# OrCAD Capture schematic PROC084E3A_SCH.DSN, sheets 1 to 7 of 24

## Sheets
1 17.LIN INTERFACE -03: size C; title: LIN INTERFACE-03; rev: E3A; note: PROC084_SCH
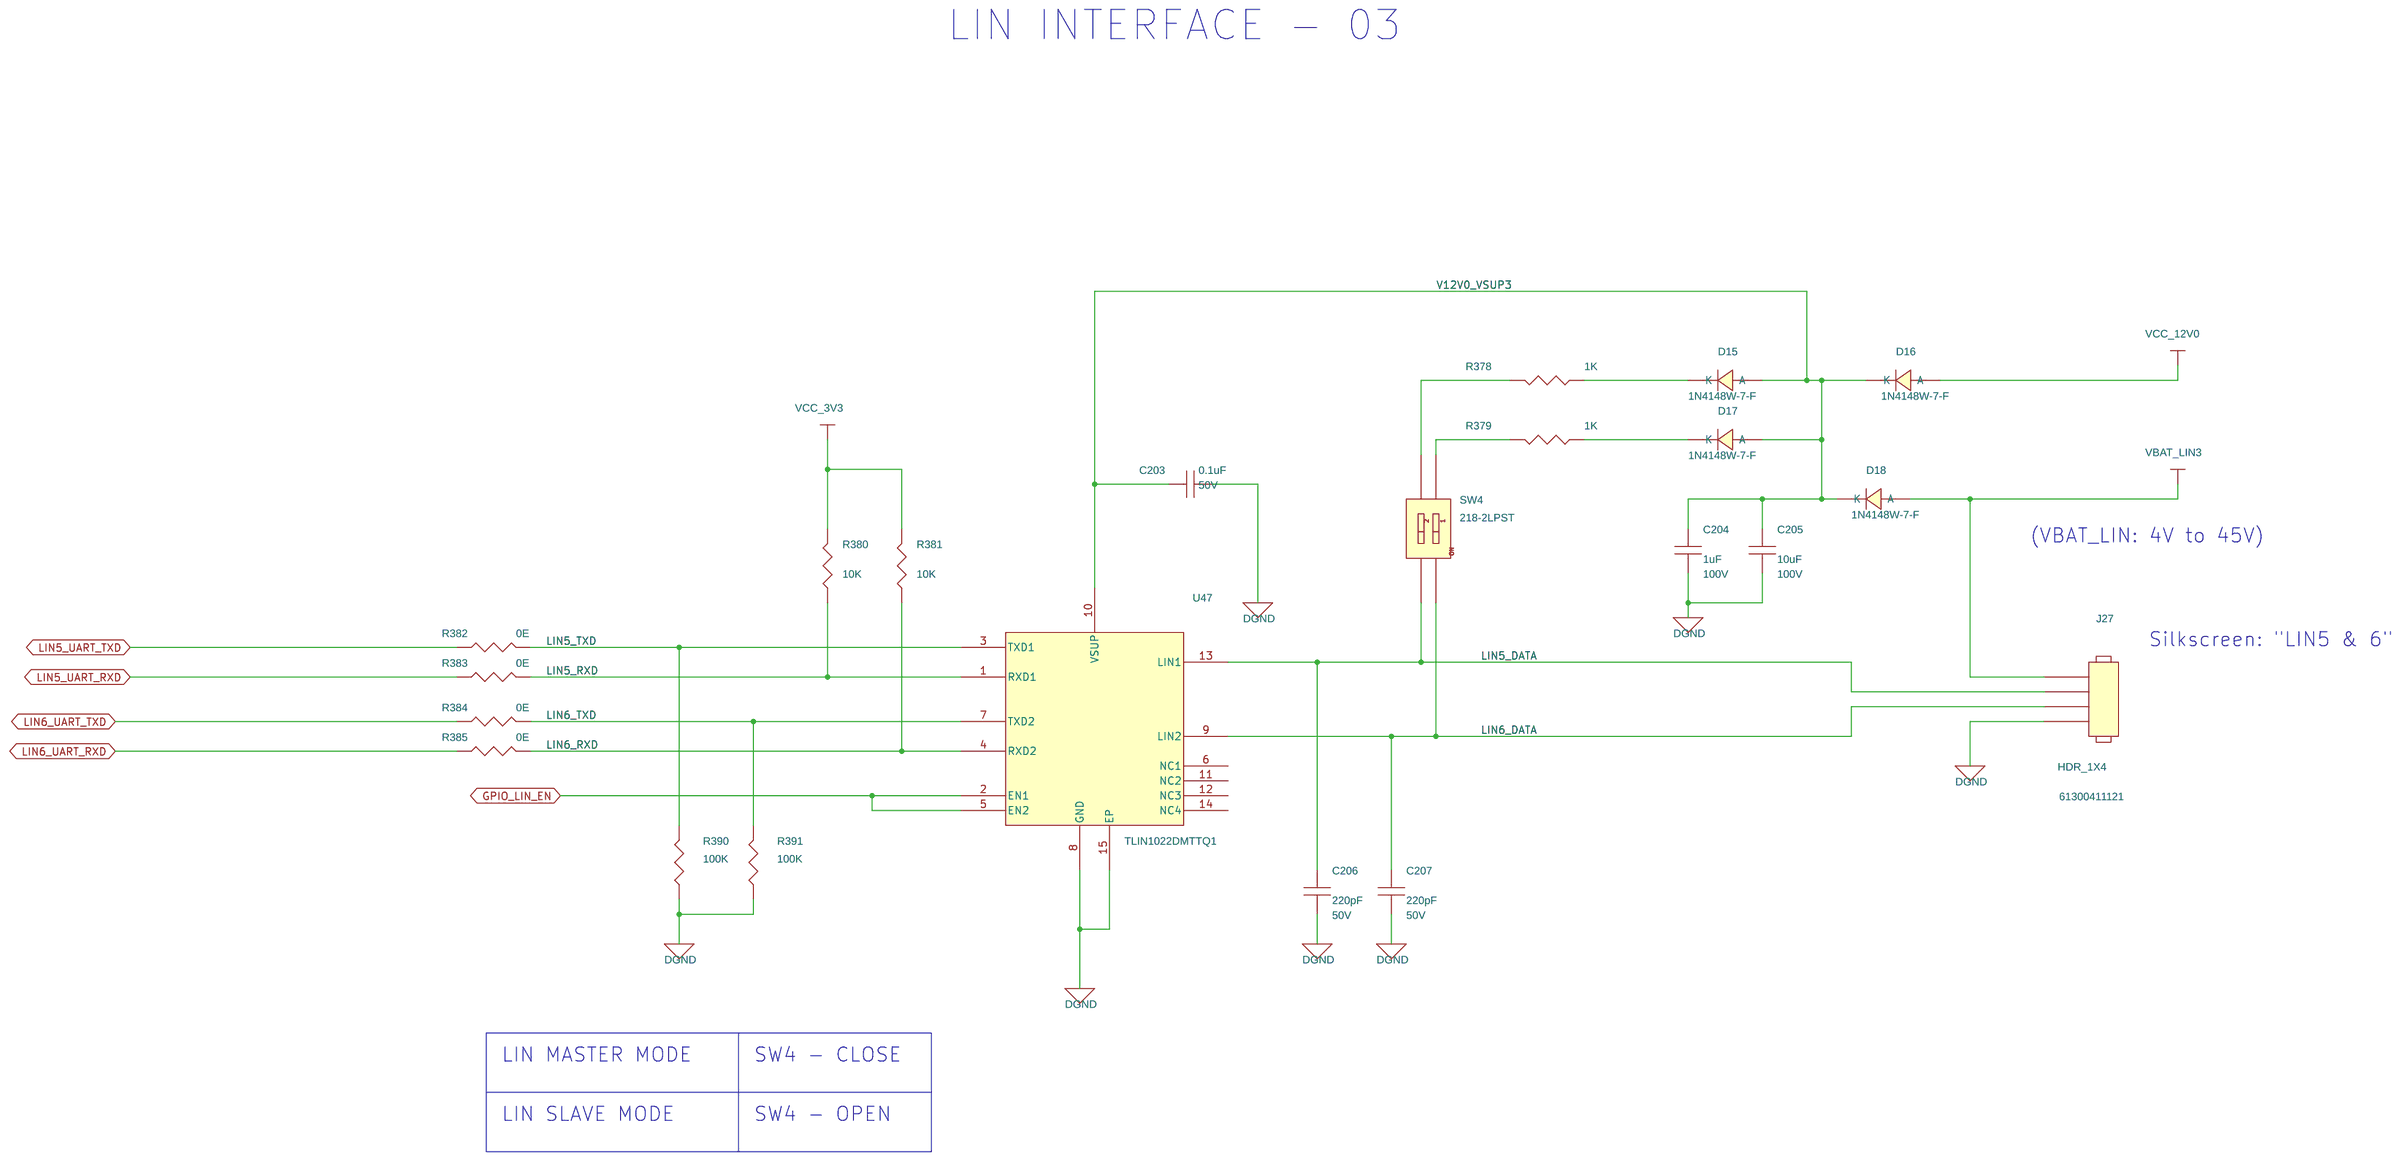
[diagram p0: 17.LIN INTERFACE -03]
2 16.LIN INTERFACE -02: size C; title: LIN INTERFACE-02
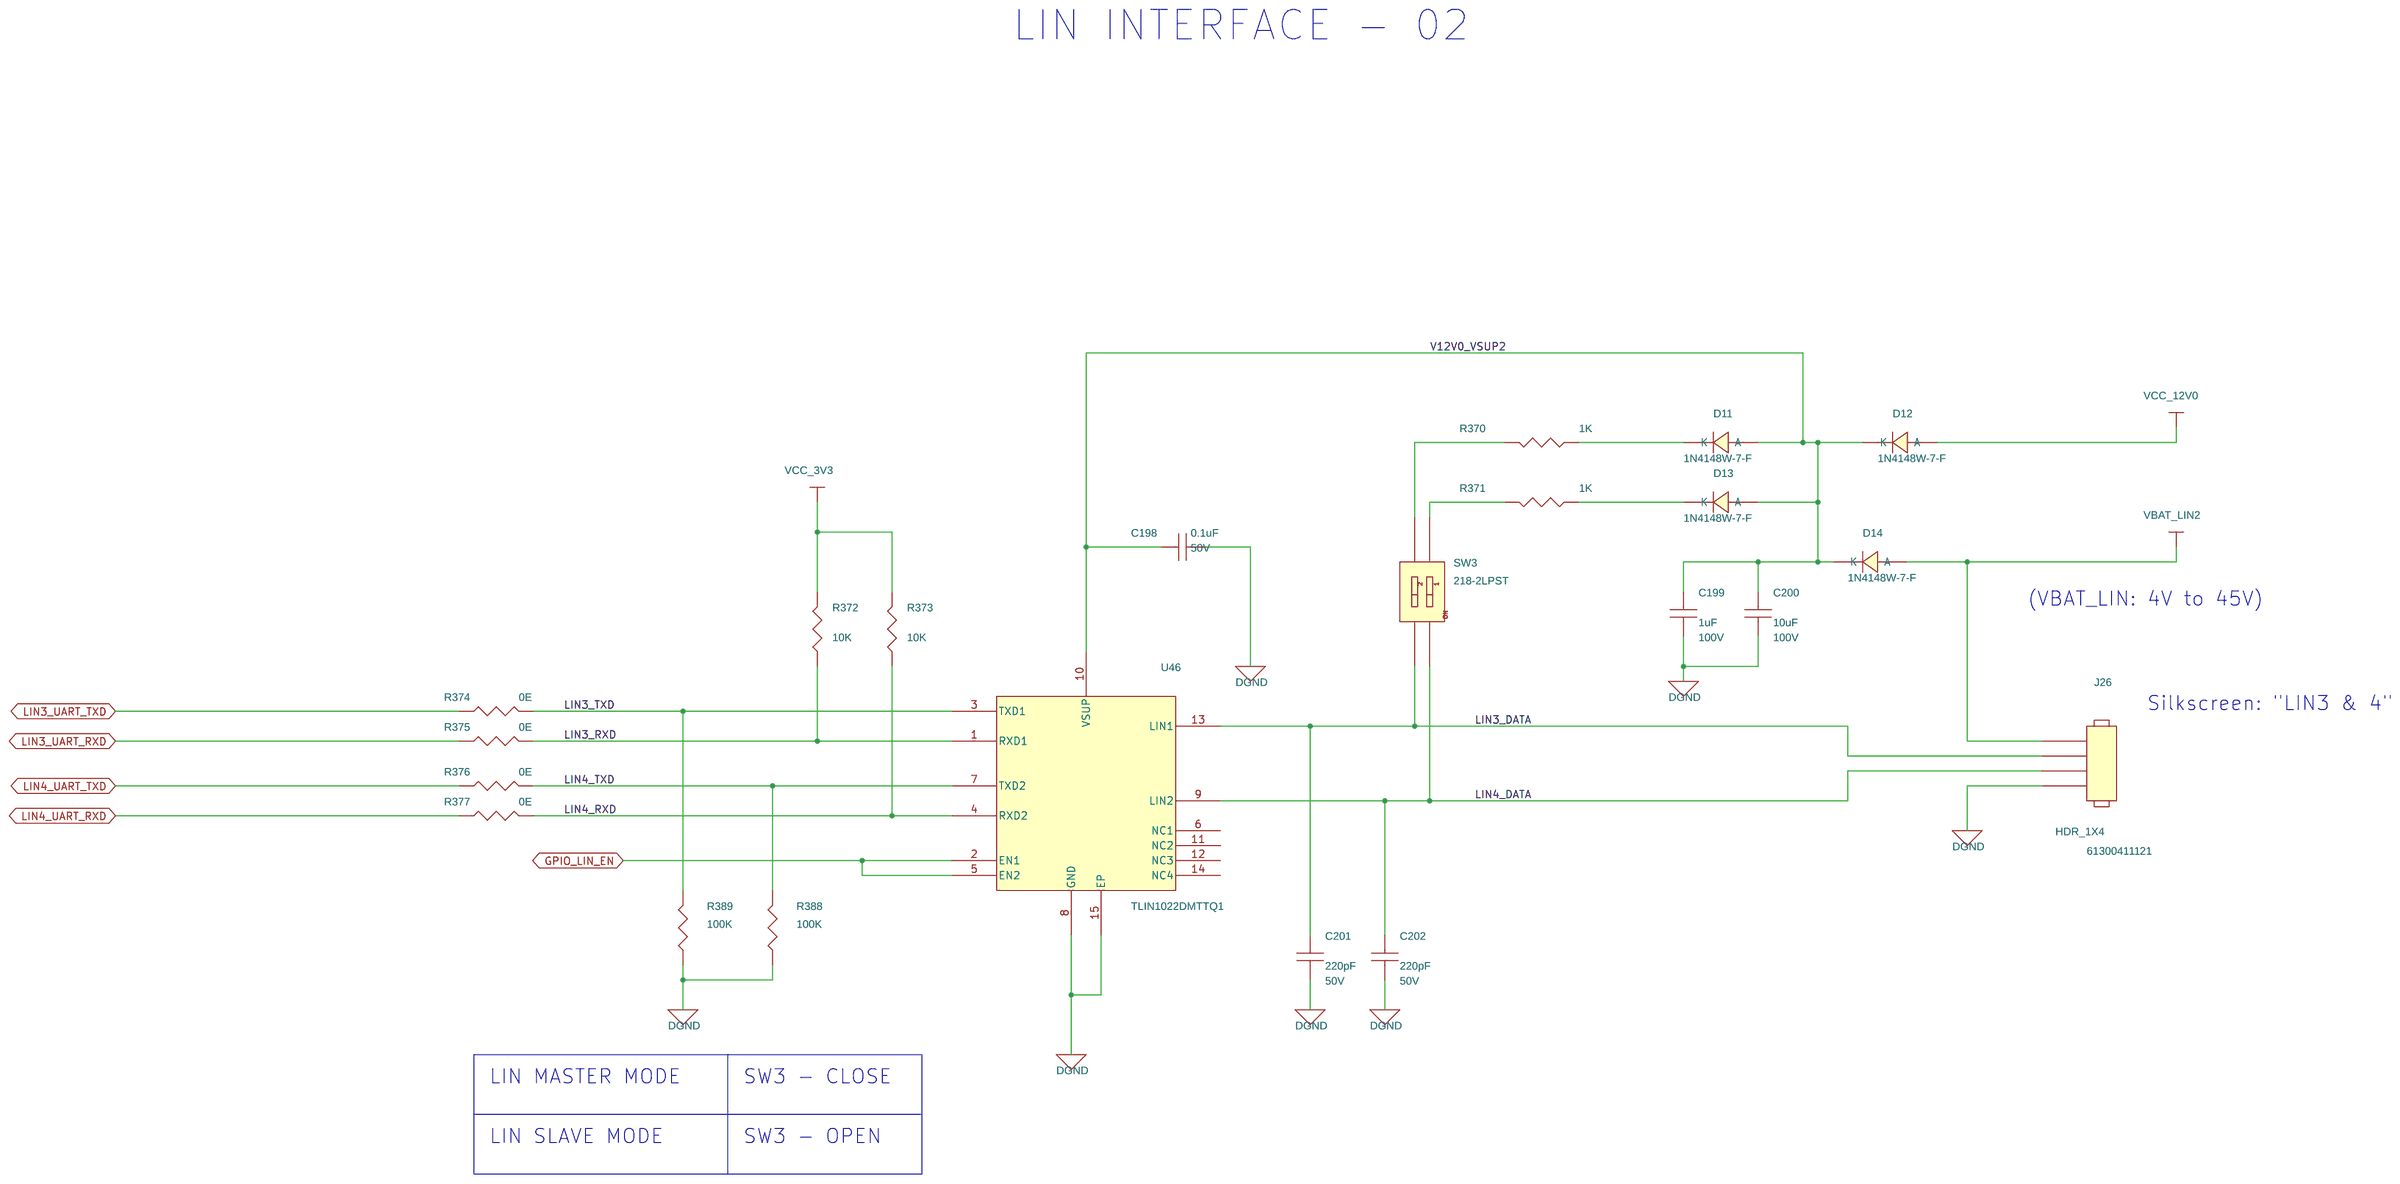
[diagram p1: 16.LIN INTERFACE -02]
3 15.LIN INTERFACE -01: size C; title: LIN INTERFACE-01
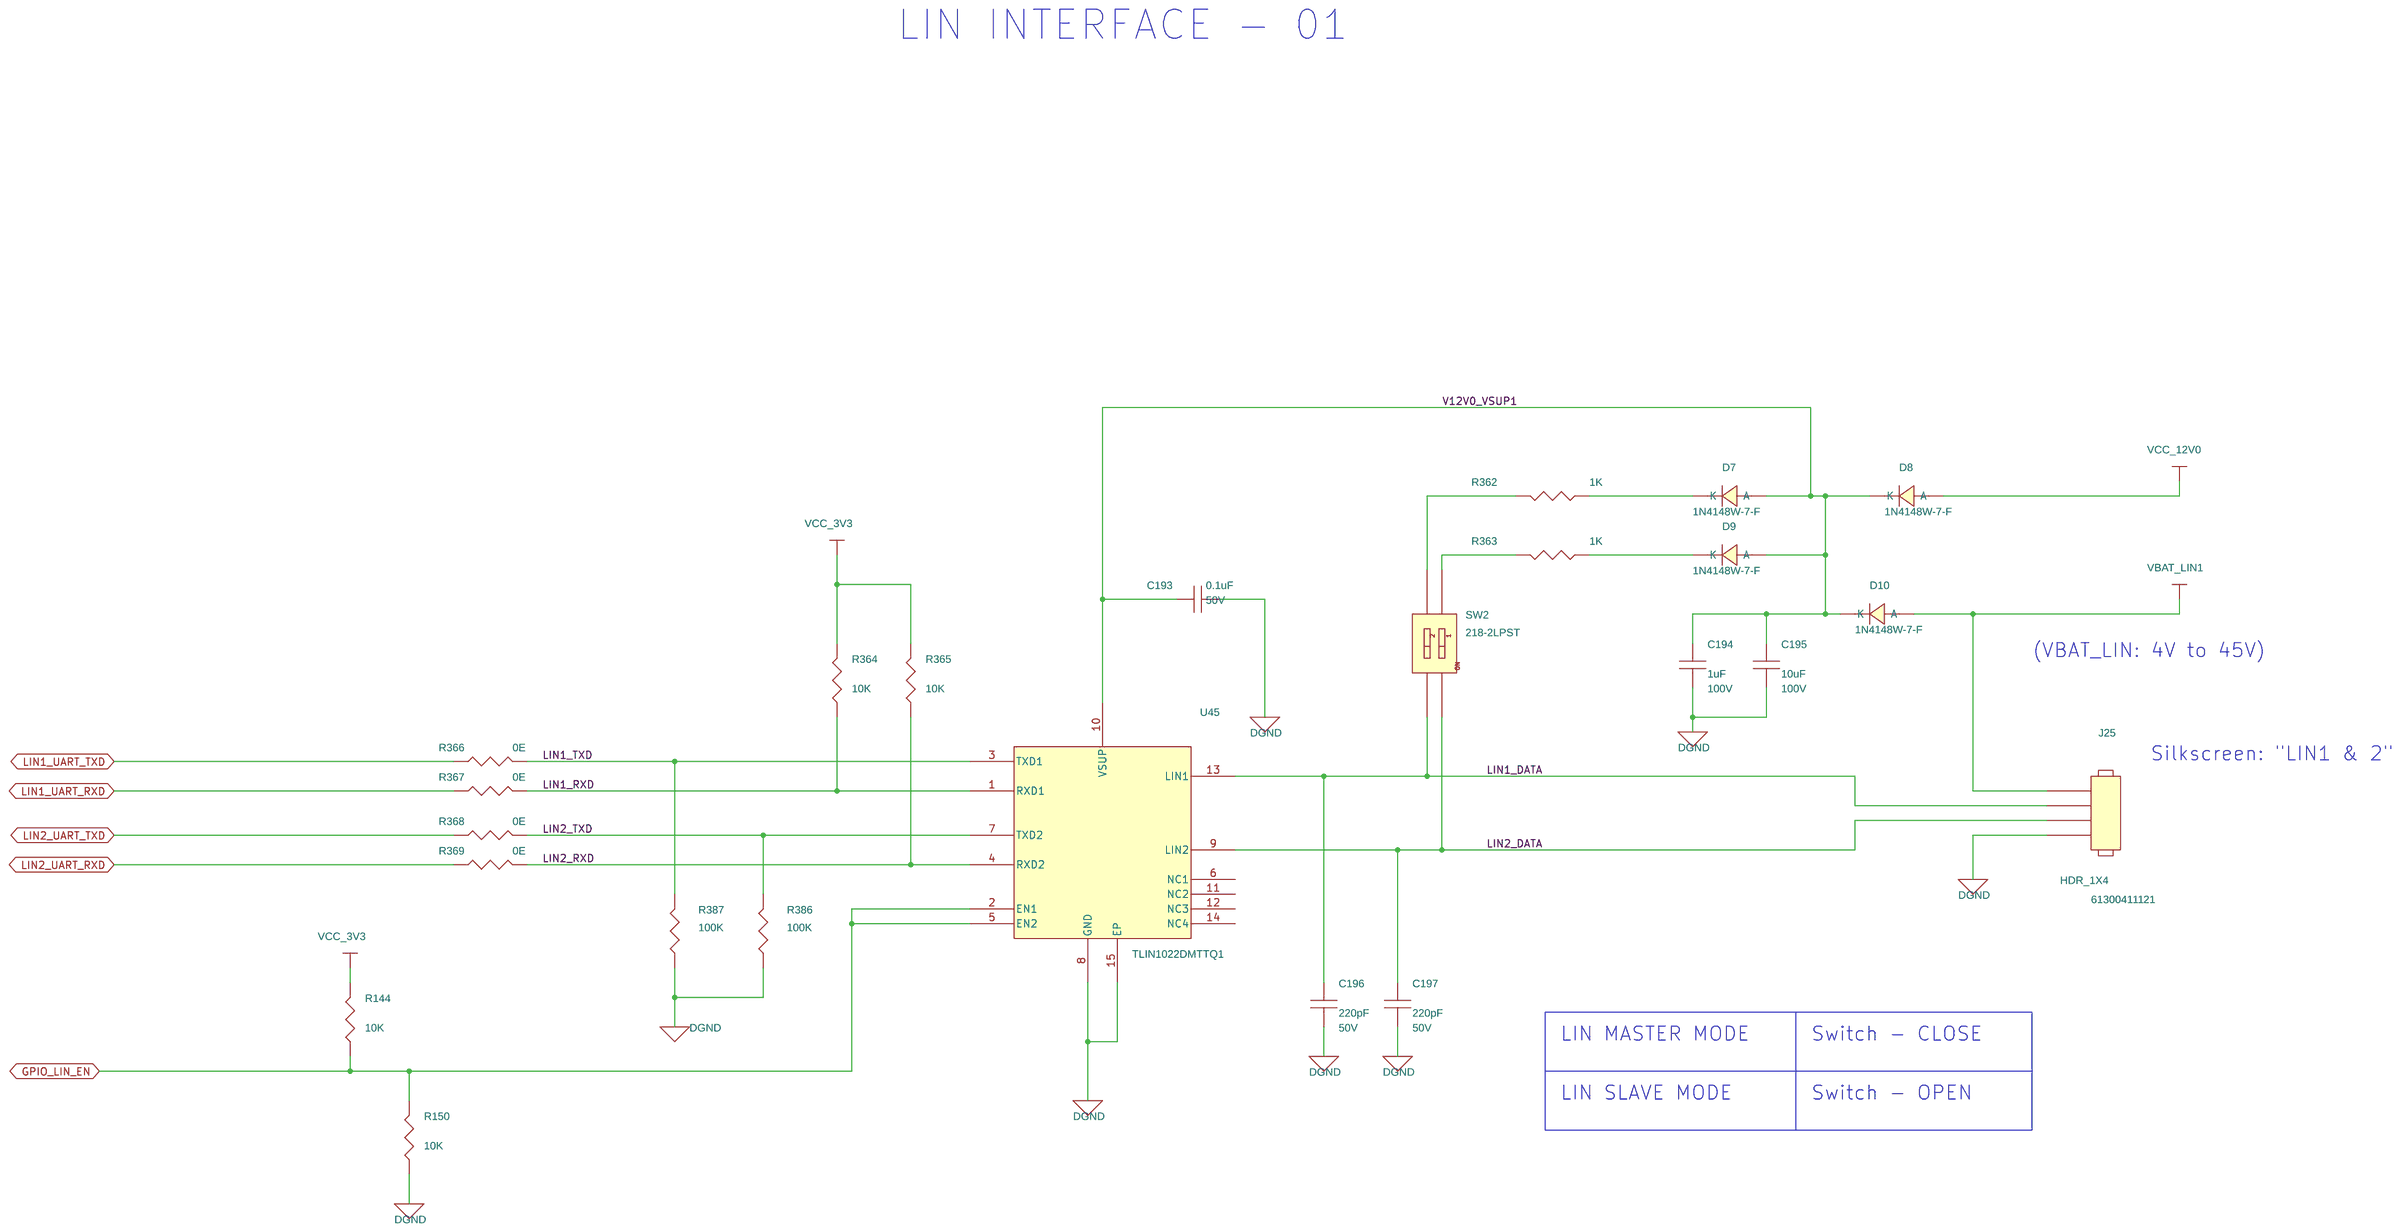
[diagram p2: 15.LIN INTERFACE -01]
4 24. HARDWARE SCHEMATICS: title: HARDWARE SCHEMATICS
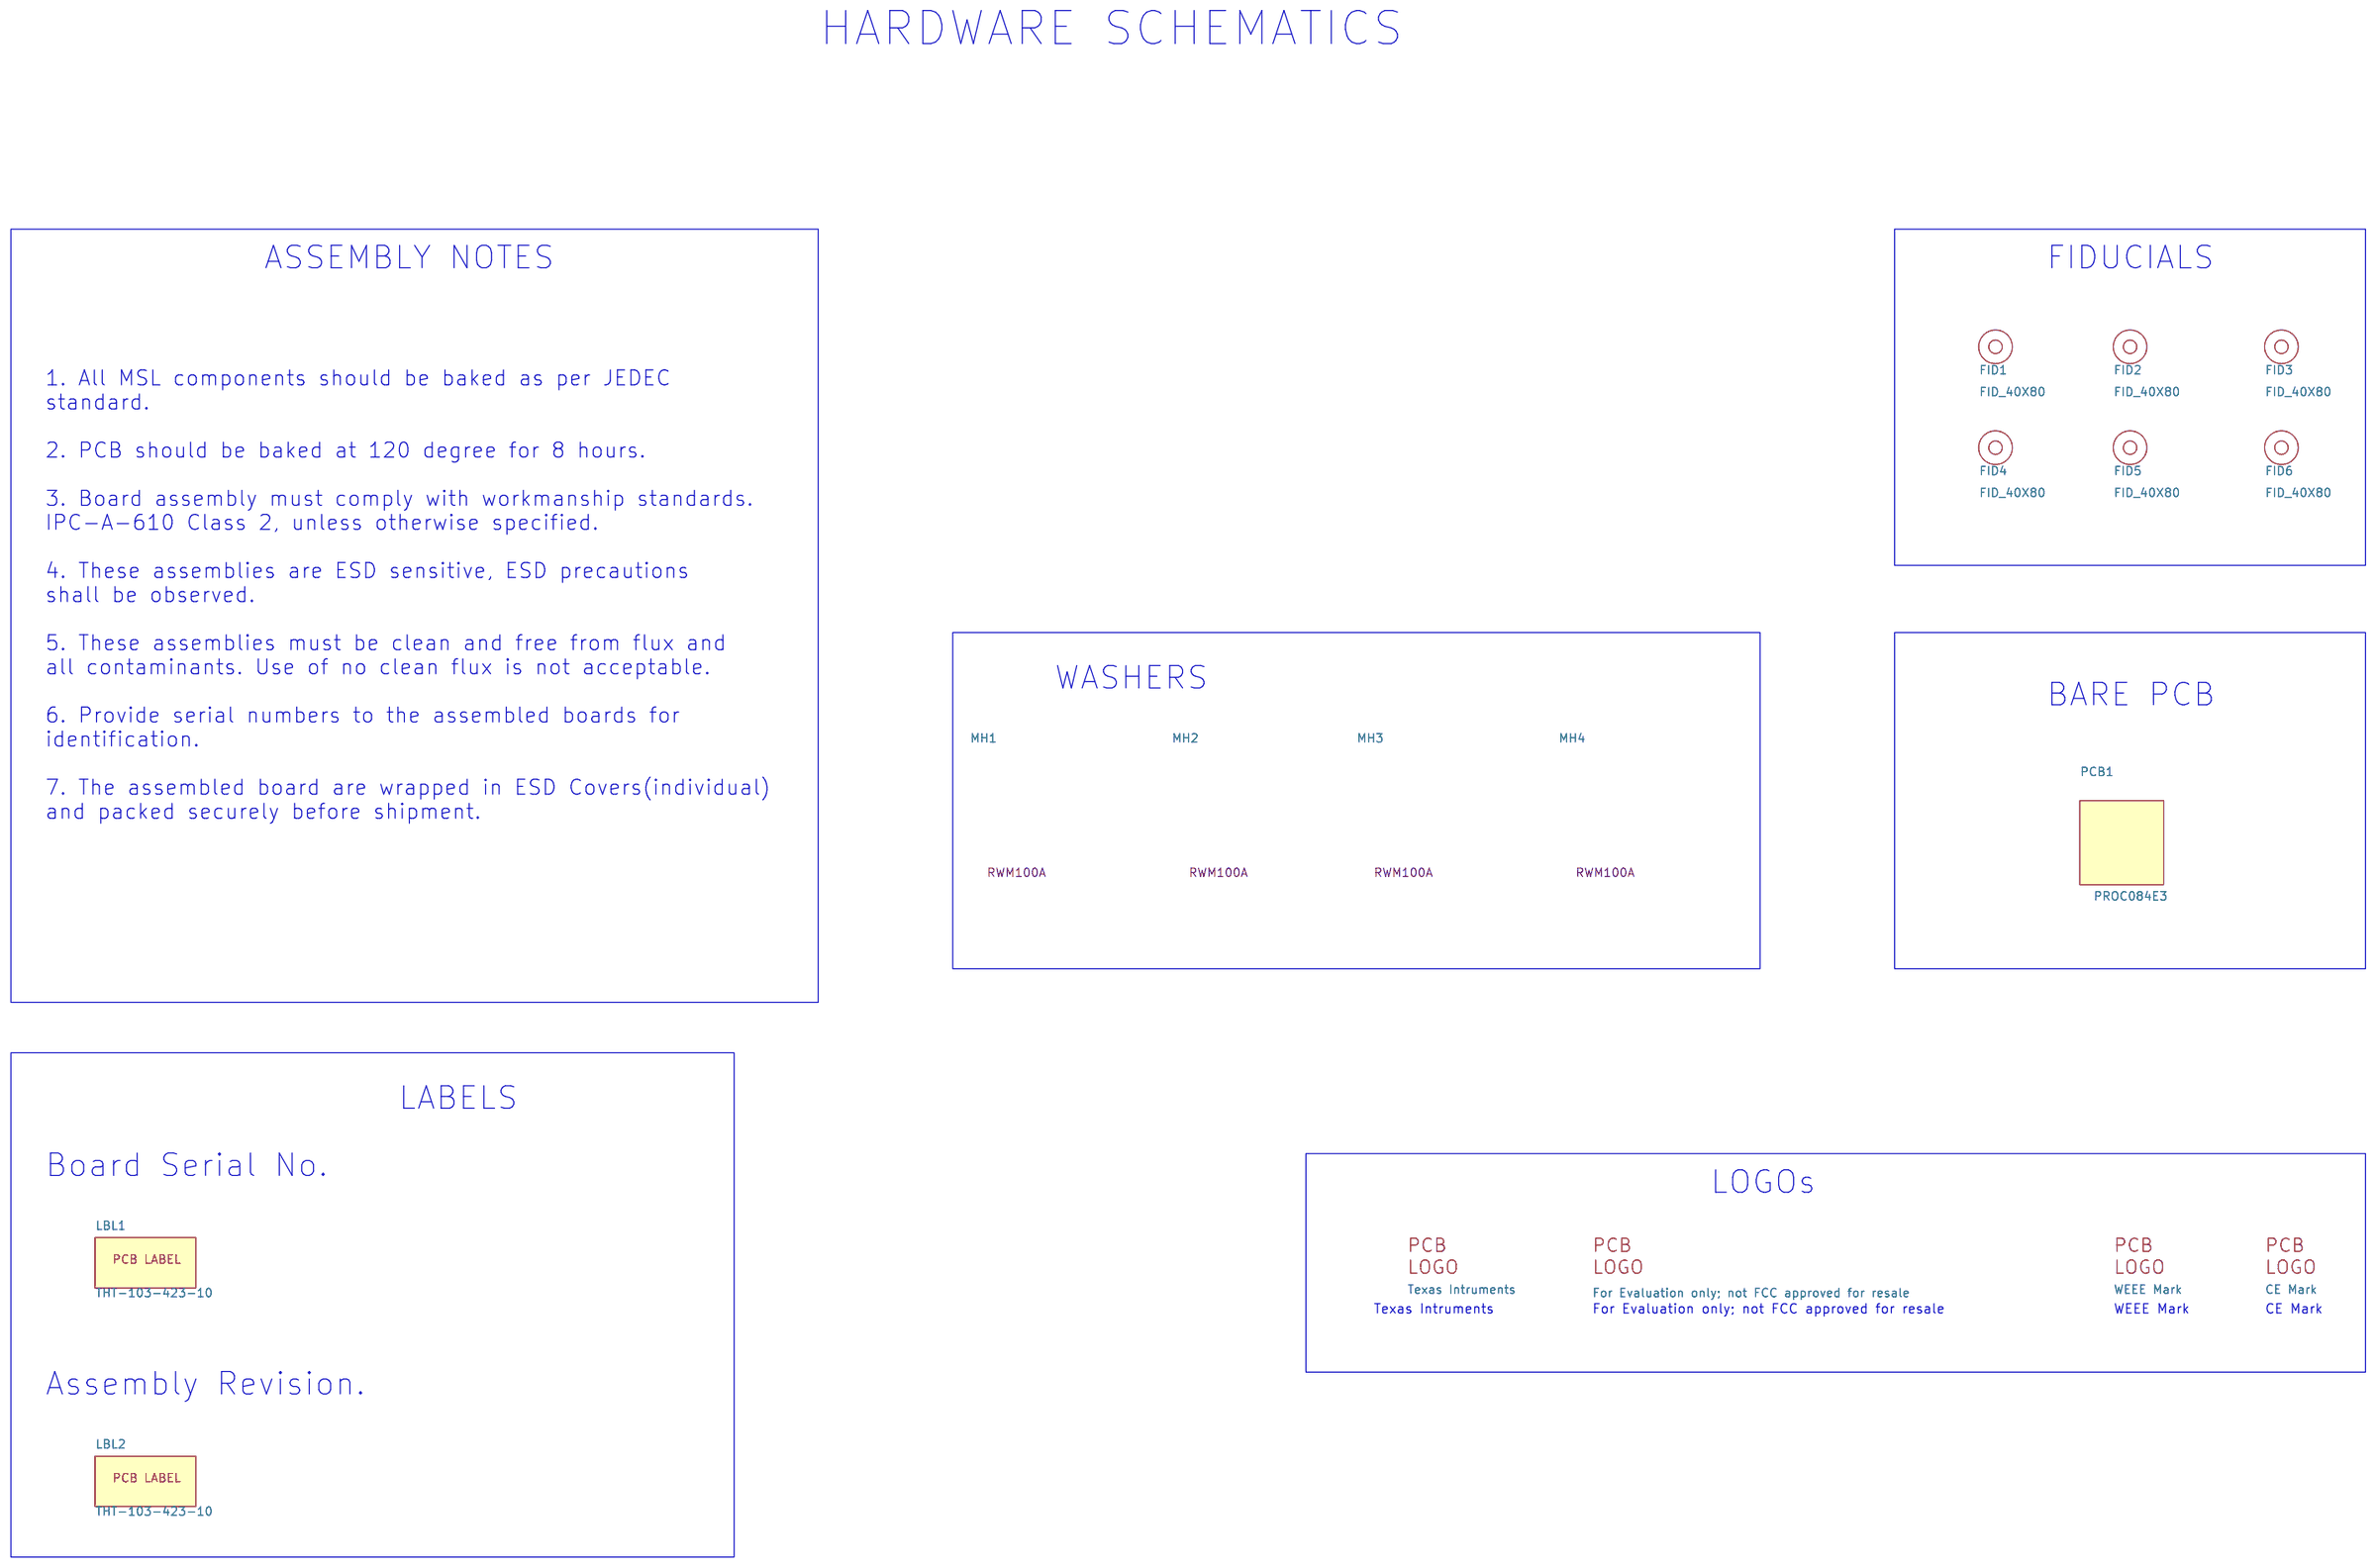
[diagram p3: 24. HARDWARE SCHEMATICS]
5 01. TABLE OF CONTENTS: title: TABLE OF CONTENTS
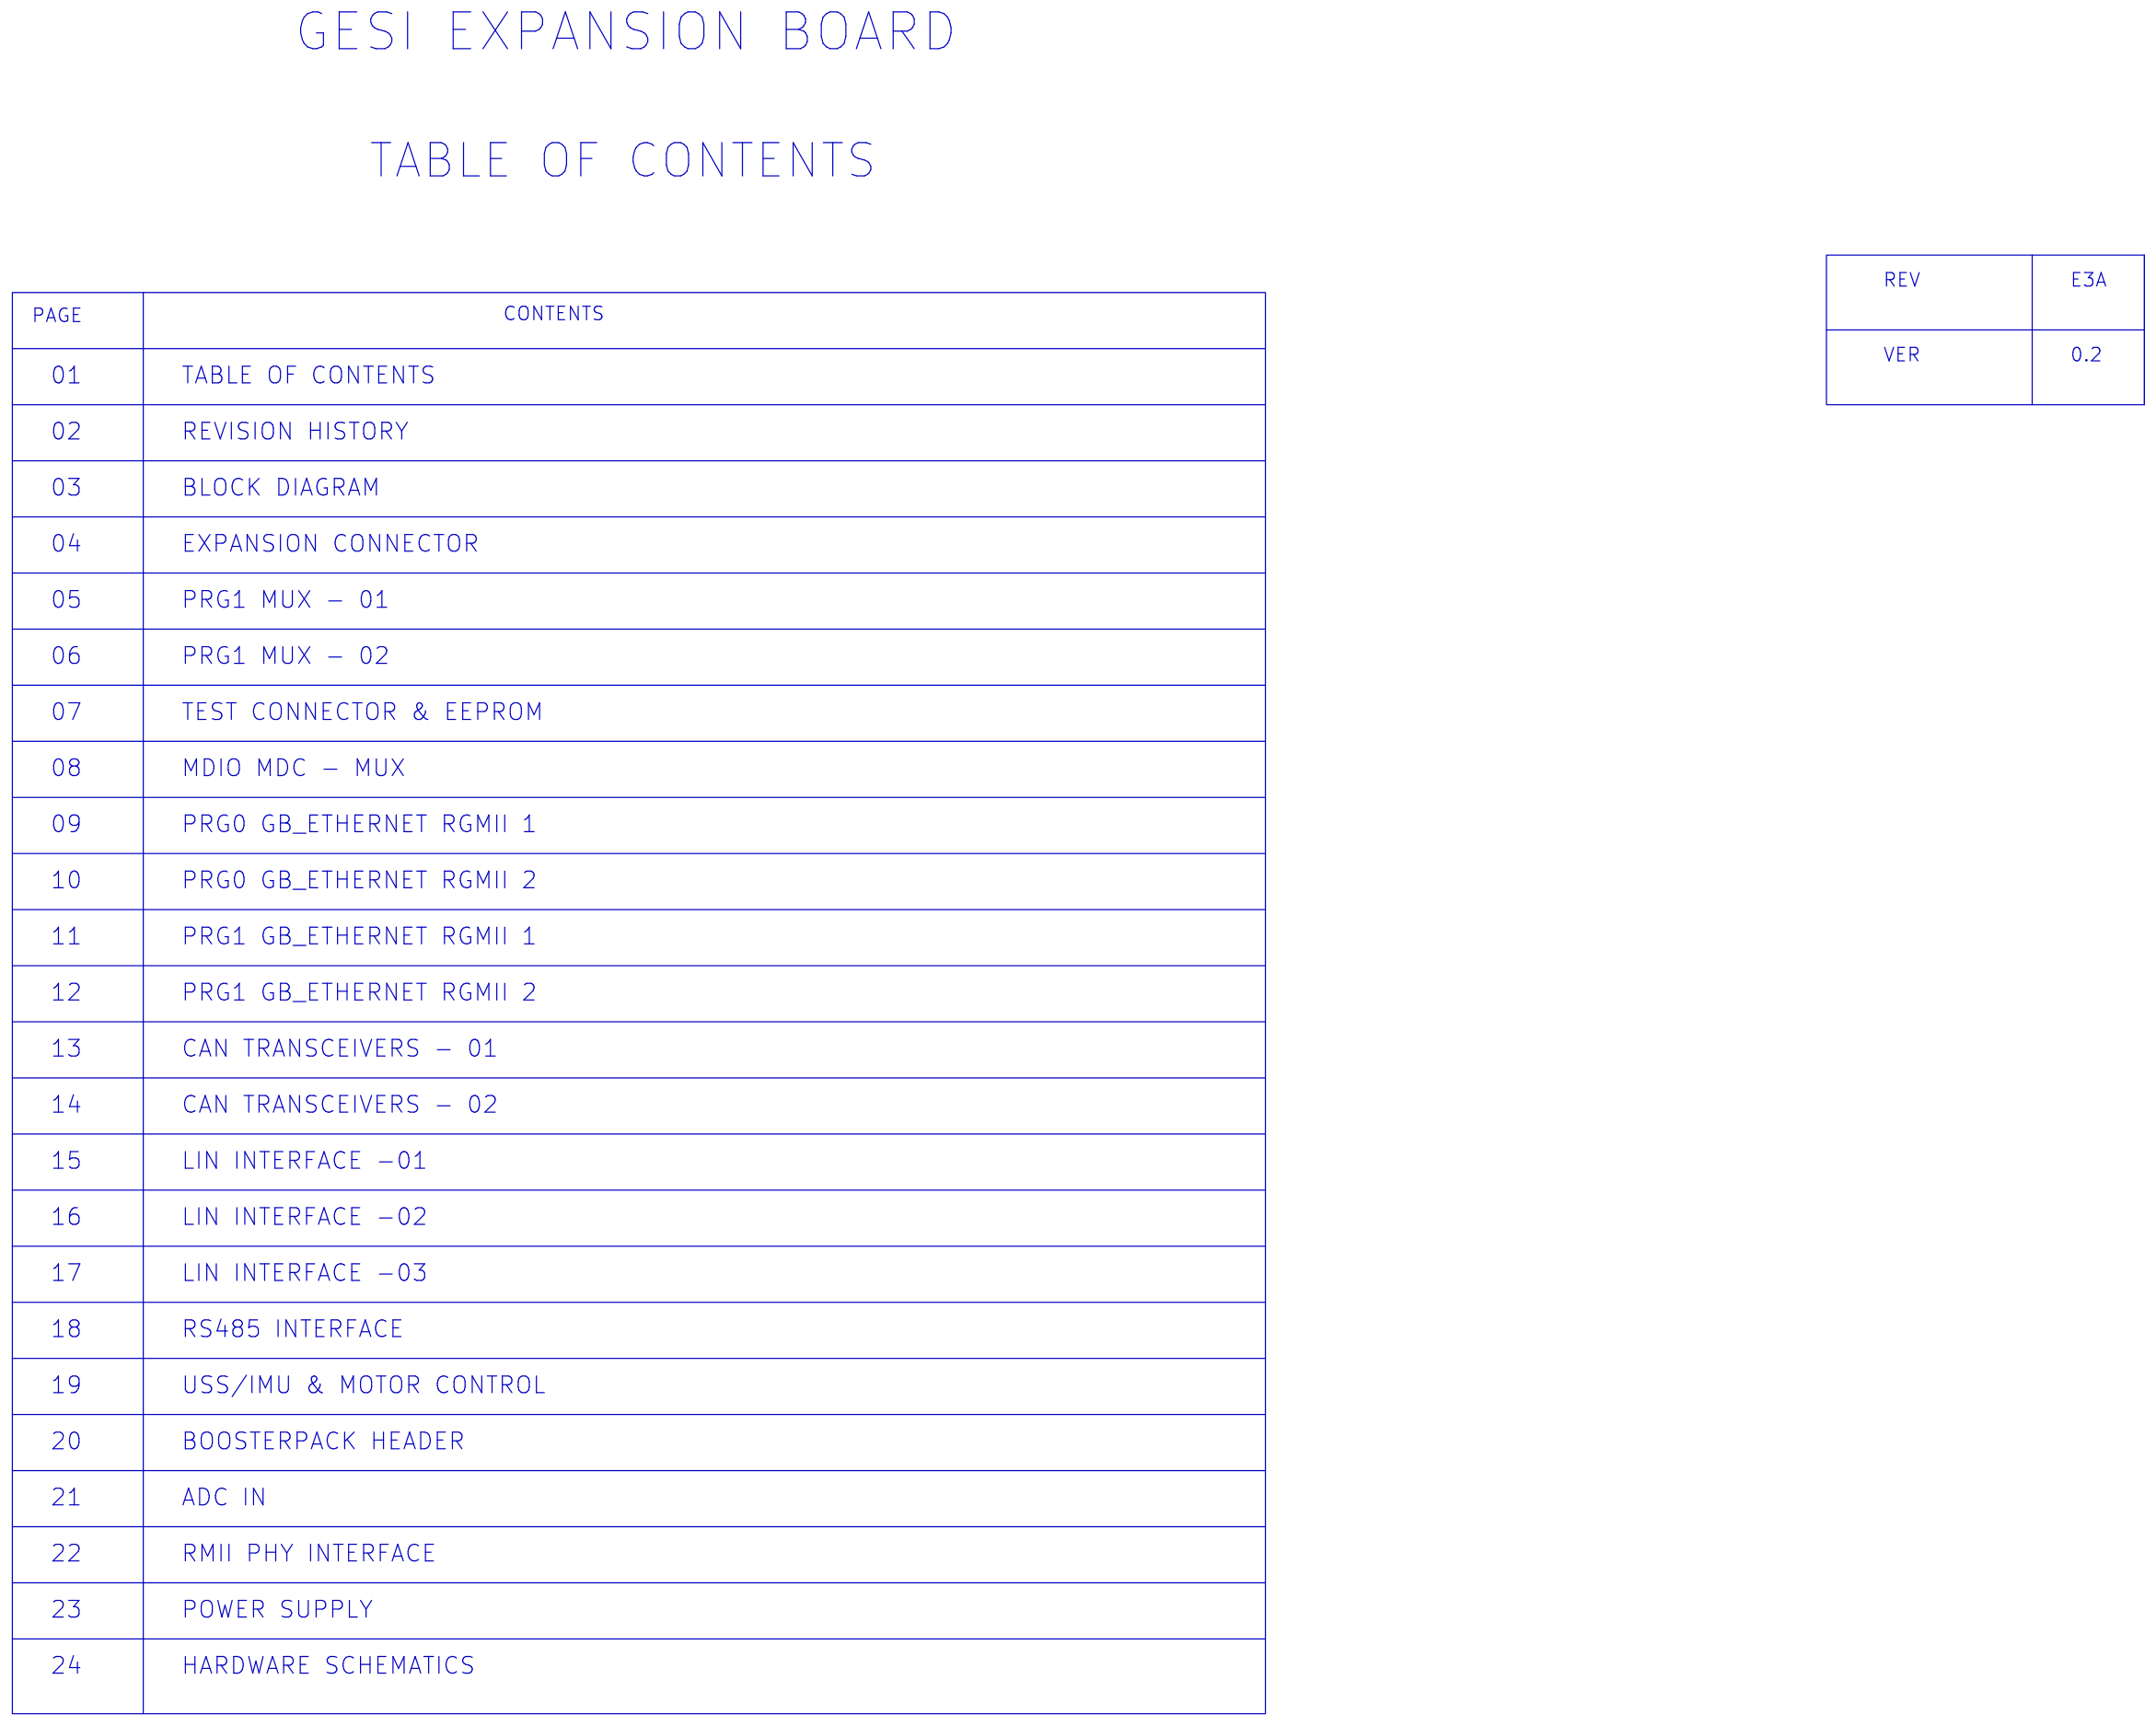
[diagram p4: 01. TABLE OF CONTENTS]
6 02. REVISION HISTORY: title: REVISION HISTORY
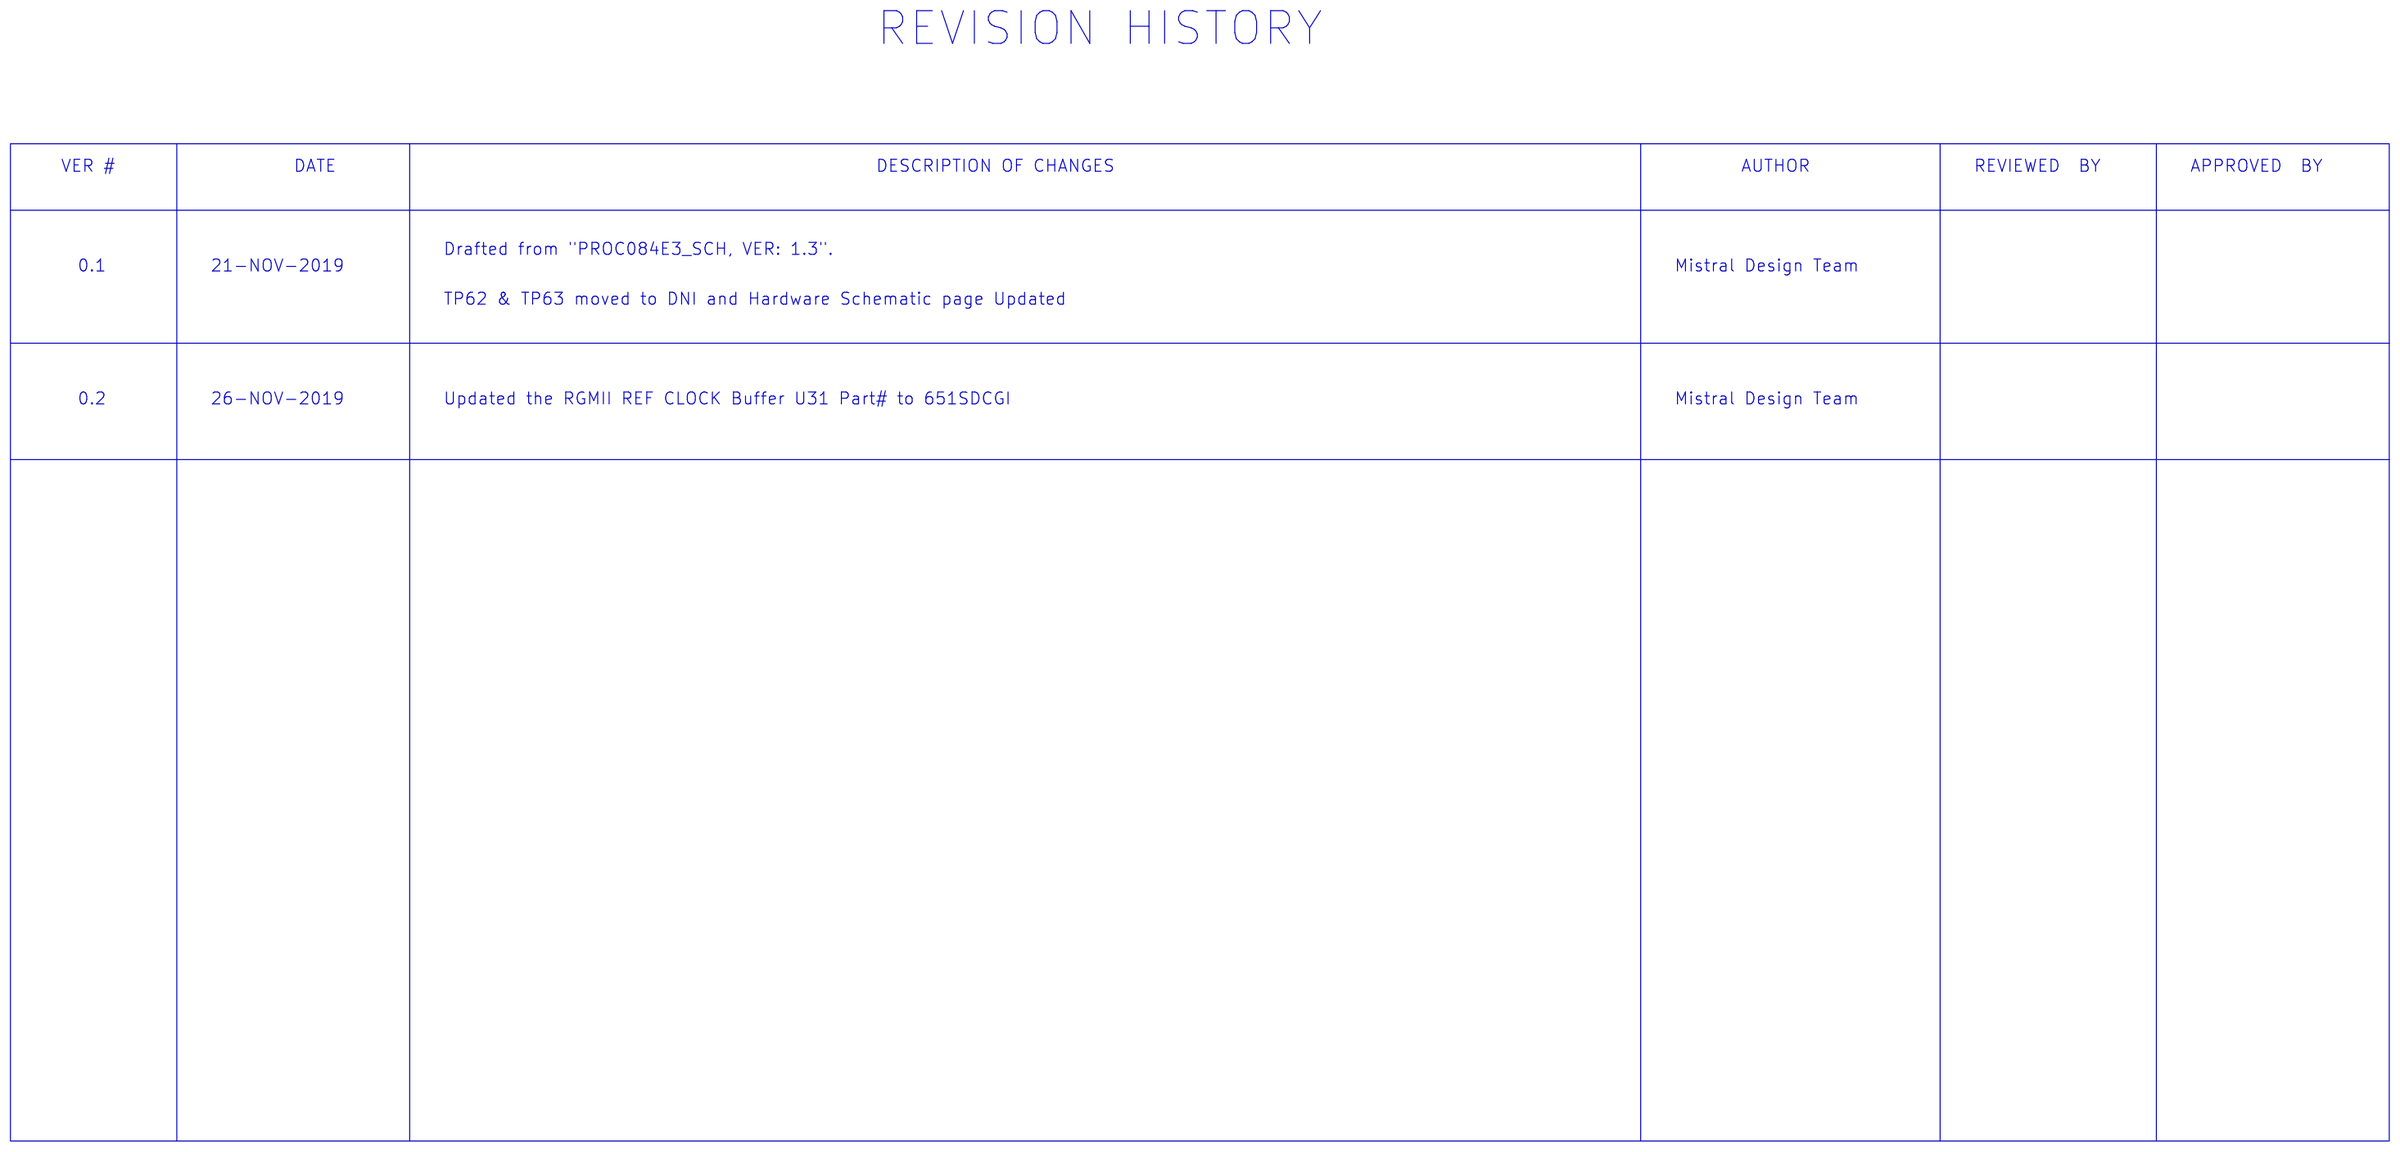
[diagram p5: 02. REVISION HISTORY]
7 03. BLOCK_DIAGRAM: title: BLOCK DIAGRAM
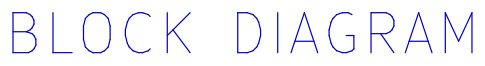
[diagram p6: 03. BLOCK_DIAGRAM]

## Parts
sheet 15.LIN INTERFACE -01
C193  0.1uF  [CAP0402_0-75]
C194  1uF  [CAP0805_1-5]
C195  10uF  [CAP1210_2-75]
C196  220pF  [CAP0402_0-75]
C197  220pF  [CAP0402_0-75]
D7  1N4148W-7-F  [DIO_SOD123_1-4]
D8  1N4148W-7-F  [DIO_SOD123_1-4]
D9  1N4148W-7-F  [DIO_SOD123_1-4]
D10  1N4148W-7-F  [DIO_SOD123_1-4]
J25  HDR_1X4  [HDR_1X4_61300411121_S_T_8-6]
R144  10K  [RES0402_0-5]
R150  10K  [RES0402_0-5]
R362  1K  [RES0402_0-5]
R363  1K  [RES0402_0-5]
R364  10K  [RES0402_0-5]
R365  10K  [RES0402_0-5]
R366  0E  [RES0402_0-5]
R367  0E  [RES0402_0-5]
R368  0E  [RES0402_0-5]
R369  0E  [RES0402_0-5]
R386  100K  [RES0402_0-5]
R387  100K  [RES0402_0-5]
SW2  218-2LPST  [SW4_49-99_150X230_SMD_2-7]
U45  TLIN1022DMTTQ1  [VSON14_25-59_120X180_0-9]
sheet 16.LIN INTERFACE -02
C198  0.1uF  [CAP0402_0-75]
C199  1uF  [CAP0805_1-5]
C200  10uF  [CAP1210_2-75]
C201  220pF  [CAP0402_0-75]
C202  220pF  [CAP0402_0-75]
D11  1N4148W-7-F  [DIO_SOD123_1-4]
D12  1N4148W-7-F  [DIO_SOD123_1-4]
D13  1N4148W-7-F  [DIO_SOD123_1-4]
D14  1N4148W-7-F  [DIO_SOD123_1-4]
J26  HDR_1X4  [HDR_1X4_61300411121_S_T_8-6]
R370  1K  [RES0402_0-5]
R371  1K  [RES0402_0-5]
R372  10K  [RES0402_0-5]
R373  10K  [RES0402_0-5]
R374  0E  [RES0402_0-5]
R375  0E  [RES0402_0-5]
R376  0E  [RES0402_0-5]
R377  0E  [RES0402_0-5]
R388  100K  [RES0402_0-5]
R389  100K  [RES0402_0-5]
SW3  218-2LPST  [SW4_49-99_150X230_SMD_2-7]
U46  TLIN1022DMTTQ1  [VSON14_25-59_120X180_0-9]
sheet 17.LIN INTERFACE -03
C203  0.1uF  [CAP0402_0-75]
C204  1uF  [CAP0805_1-5]
C205  10uF  [CAP1210_2-75]
C206  220pF  [CAP0402_0-75]
C207  220pF  [CAP0402_0-75]
D15  1N4148W-7-F  [DIO_SOD123_1-4]
D16  1N4148W-7-F  [DIO_SOD123_1-4]
D17  1N4148W-7-F  [DIO_SOD123_1-4]
D18  1N4148W-7-F  [DIO_SOD123_1-4]
J27  HDR_1X4  [HDR_1X4_61300411121_S_T_8-6]
R378  1K  [RES0402_0-5]
R379  1K  [RES0402_0-5]
R380  10K  [RES0402_0-5]
R381  10K  [RES0402_0-5]
R382  0E  [RES0402_0-5]
R383  0E  [RES0402_0-5]
R384  0E  [RES0402_0-5]
R385  0E  [RES0402_0-5]
R390  100K  [RES0402_0-5]
R391  100K  [RES0402_0-5]
SW4  218-2LPST  [SW4_49-99_150X230_SMD_2-7]
U47  TLIN1022DMTTQ1  [VSON14_25-59_120X180_0-9]
sheet 24. HARDWARE SCHEMATICS
FID1  FID_40X80  [FID_40X80]
FID2  FID_40X80  [FID_40X80]
FID3  FID_40X80  [FID_40X80]
FID4  FID_40X80  [FID_40X80]
FID5  FID_40X80  [FID_40X80]
FID6  FID_40X80  [FID_40X80]
LBL1  THT-103-423-10  [NA]
LBL2  THT-103-423-10  [NA]
LOGO1  Texas Intruments  [TI_Stacked_Overlay_Small]
LOGO2  For Evaluation only; not FCC approved for resale  [FCC_disclaimer]
LOGO3  WEEE Mark  [TI_Stacked_Overlay_Small]
LOGO4  CE Mark  [TI_Stacked_Overlay_Small]
MH1  FLAT WASHER_M3  [NA]
MH2  FLAT WASHER_M3  [NA]
MH3  FLAT WASHER_M3  [NA]
MH4  FLAT WASHER_M3  [NA]
PCB1  PROC084E3

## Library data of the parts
C193 C198 C203 = CAP: CAP CERAMIC 0.1uF 50V 10% X7R 0402; Chkd/date: VASANTHA/281216; Crtd /date: CHAITHANYA/051011; Custom_Duty: 15%; Customs_HS_Code: 85322990; Distributor_name: DIGIKEY; Distributor_part_number: 445-173610-1-ND; Footprint Path: Y:\MIS_DATABASE\Library\ALTIUM_TOOL\PCB_FOOTPRINTS\Altium_Footprint_Lib.PcbLib; Height: 0.60MM; Library Path: Y:\MIS_DATABASE\Library\ALTIUM_TOOL\SCHEMATICS_PARTS\MS_DISCRETE_Library.schlib; Mfr_name: TDK CORPORATION; Mfr_part_number: C1005X7R1H104K050BE; Mistral Part No: 120011100014-R; Package: 0402; Part_type: CAPACITORS\CERAMIC; Project: VP-4000-BASE-BOARD; RoHS: RoHS; Temperature: -55°C+125°C; Tolerance: 10%; Voltage: 50V; Wattage: NA; Weight: 0.65mg; Datasheet: Y:\MIS_DATABASE\DATASHEETS\CAPACITORS\TDK_C-SER_FEB19.PDF
C194 C199 C204 = CAP: CAP CERAMIC 1uF 100V 10% X7S 0805; Chkd/date: VASANTHA/170217; Crtd /date: USMAN/190313; Custom_Duty: 15%; Customs_HS_Code: 85322990; Distributor_name: DIGIKEY; Distributor_part_number: 445-5205-1-ND; Footprint Path: Y:\MIS_DATABASE\Library\ALTIUM_TOOL\PCB_FOOTPRINTS\Altium_Footprint_Lib.PcbLib; Height: 1.45MM; Library Path: Y:\MIS_DATABASE\Library\ALTIUM_TOOL\SCHEMATICS_PARTS\MS_DISCRETE_Library.schlib; Mfr_name: TDK CORPORATION; Mfr_part_number: C2012X7S2A105K125AB; Mistral Part No: 120013030002-R; Package: 0805; Part_type: CAPACITORS\CERAMIC; Project: DTRM; RoHS: RoHS; Temperature: -55°C+125°C; Tolerance: 10%; Voltage: 100V; Wattage: NA; Weight: 5.5mg; Datasheet: Y:\MIS_DATABASE\DATASHEETS\CAPACITORS\C5750-X7S.PDF
C195 C200 C205 = CAP: CAP CERAMIC 10uF 100V 10% X7S 1210; Chkd/date: MANIRAJA/280819; Crtd /date: MANIRAJA/280819; Custom_Duty: 15%; Customs_HS_Code: 85322990; Distributor_name: DIGIKEY; Distributor_part_number: 490-16266-1-ND; Footprint Path: Y:\MIS_DATABASE\Library\ALTIUM_TOOL\PCB_FOOTPRINTS\Altium_Footprint_Lib.PcbLib; Height: 2.70MM; Library Path: Y:\MIS_DATABASE\Library\ALTIUM_TOOL\SCHEMATICS_PARTS\MS_DISCRETE_Library.schlib; Mfr_name: MURATA; Mfr_part_number: GRM32EC72A106KE05L; Mistral Part No: 120019080009-R; Package: 1210; Part_type: CAPACITORS\CERAMIC; Project: TI_J7ES_GESI_EXP_BOARD; RoHS: RoHS; Temperature: -55°C+125°C; Tolerance: 10%; Voltage: 100V; Wattage: NA; Weight: 110mg; Datasheet: Y:\MIS_DATABASE\DATASHEETS\CAPACITORS\GRM32EC72A106KE05.PDF
C196 C197 C201 C202 C206 C207 = CAP: CAP CERAMIC 220pF 50V 2% C0G(NP0) 0402; Chkd/date: MANIRAJA/030619; Crtd /date: ALVY/310519; Custom_Duty: 15%; Customs_HS_Code: 85322990; Distributor_name: DIGIKEY; Distributor_part_number: 311-3739-1-ND; Footprint Path: Y:\MIS_DATABASE\Library\ALTIUM_TOOL\PCB_FOOTPRINTS\Altium_Footprint_Lib.PcbLib; Height: 0.55MM; Library Path: Y:\MIS_DATABASE\Library\ALTIUM_TOOL\SCHEMATICS_PARTS\MS_DISCRETE_Library.schlib; Mfr_name: YAGEO AMERICA; Mfr_part_number: CC0402GRNPO9BN221; Mistral Part No: 120014070004-R; Package: 0402; Part_type: CAPACITORS\CERAMIC; Project: J7ES_SOM_DUAL-LEO_PMIC; RoHS: RoHS; Temperature: -55°C+125°C; Tolerance: 2%; Voltage: 50V; Wattage: NA; Weight: 0.65mg; Datasheet: Y:\MIS_DATABASE\DATASHEETS\CAPACITORS\YACC-NPO.PDF
D7-D18 = DIODE: DIODE SWITCH 400mW 100V SOD123; Chkd/date: VASANTHA/220317; Crtd /date: MANIRAJA/150317; Custom_Duty: 15%; Customs_HS_Code: 85412900; Distributor_name: DIGIKEY; Distributor_part_number: 1N4148W-FDICT-ND; Height: 1.35MM; Mfr_name: DIODES INC; Mistral Part No: 130009030246-R; Package: SOD123; Part_type: DIODE\SWITCHING; Project: REVA-IBMS; RoHS: RoHS; Temperature: -65°C+150°C; Tolerance: NA; Voltage: 100V; Wattage: 400mW; Weight: 0.01g; Datasheet: Y:\MIS_DATABASE\DATASHEETS\DISCRETES\DIODES\1N4148W.PDF
J25-J27 = HEADER_4X1: CON HDR 1X4 2.54MM PITCH ST TH; Chkd/date: MANIRAJA/210918; Crtd /date: ALVY/210918; Custom_Duty: 24%; Customs_HS_Code: 85369090; Distributor_name: DIGIKEY; Distributor_part_number: 732-5317-ND; Footprint Path: Y:\MIS_DATABASE\Library\ALTIUM_TOOL\PCB_FOOTPRINTS\Altium_Footprint_Lib.PcbLib; Height: 8.54MM; Library Path: Y:\MIS_DATABASE\Library\ALTIUM_TOOL\SCHEMATICS_PARTS\MS_CONNECTOR_Library.schlib; Mfr_name: WURTH ELECTRONICS INC; Mfr_part_number: 61300411121; Mistral Part No: 150018090038-R; Package: THRU-HOLE; Part_type: CONNECTOR\HEADERS; Project: TI_60GHz-AOP; RoHS: RoHS; Temperature: -40°C+105°C; Tolerance: NA; Voltage: NA; Wattage: NA; Weight: 210mg; Datasheet: Y:\MIS_DATABASE\DATASHEETS\CONNECTORS\6130XXX.PDF
R144 R150 R364 R365 R372 R373 R380 R381 = RESISTOR: RES 10K 1/16W 5% 0402; Chkd/date: VASANTHA/061216; Crtd /date: MAZHAR/230805; Custom_Duty: 15%; Customs_HS_Code: 85332119; Distributor_name: DIGIKEY; Distributor_part_number: 311-10KJRCT-ND; Footprint Path: Y:\MIS_DATABASE\Library\ALTIUM_TOOL\PCB_FOOTPRINTS\Altium_Footprint_Lib.PcbLib; Height: 0.40MM; Library Path: Y:\MIS_DATABASE\Library\ALTIUM_TOOL\SCHEMATICS_PARTS\MS_DISCRETE_Library.schlib; Mfr_name: YAGEO AMERICA; Mfr_part_number: RC0402JR-0710KL; Mistral Part No: 110011060021-R; Package: 0402; Part_type: RESISTORS\FIXED; Project: HSE; RoHS: RoHS; Temperature: -55°C+155°C; Tolerance: 5%; Voltage: NA; Wattage: 1/16W; Weight: 0.65mg; Datasheet: Y:\MIS_DATABASE\DATASHEETS\RESISTORS\RCXXXXL-SER_MAR18.PDF
R362 R363 R370 R371 R378 R379 = RESISTOR: RES 1K 1/16W 5% 0402; Chkd/date: VASANTHA/120516; Crtd /date: VASANTHA/120516; Custom_Duty: 15%; Customs_HS_Code: 85332119; Distributor_name: DIGIKEY; Distributor_part_number: 311-1.0KJRCT-ND; Footprint Path: Y:\MIS_DATABASE\Library\ALTIUM_TOOL\PCB_FOOTPRINTS\Altium_Footprint_Lib.PcbLib; Height: 0.40MM; Library Path: Y:\MIS_DATABASE\Library\ALTIUM_TOOL\SCHEMATICS_PARTS\MS_DISCRETE_Library.schlib; Mfr_name: YAGEO AMERICA; Mfr_part_number: RC0402JR-071KL; Mistral Part No: 110010070006-R; Package: 0402; Part_type: RESISTORS\FIXED; Project: TMDXCSK368; RoHS: RoHS; Temperature: -55°C+155°C; Tolerance: 5%; Voltage: NA; Wattage: 1/16W; Weight: 0.65mg; Datasheet: Y:\MIS_DATABASE\DATASHEETS\RESISTORS\RCXXXXL-SER_MAR18.PDF
R366-R369 R374-R377 R382-R385 = RESISTOR: RES 0E 1/10W JUMPER 0402; Chkd/date: MANIRAJA/290318; Crtd /date: ALVY/270318; Custom_Duty: 15%; Customs_HS_Code: 85332119; Distributor_name: DIGIKEY; Distributor_part_number: MCS0402-0.0-ZZCT-ND; Footprint Path: Y:\MIS_DATABASE\Library\ALTIUM_TOOL\PCB_FOOTPRINTS\Altium_Footprint_Lib.PcbLib; Height: 0.37MM; Library Path: Y:\MIS_DATABASE\Library\ALTIUM_TOOL\SCHEMATICS_PARTS\MS_DISCRETE_Library.schlib; Mfr_name: VISHAY; Mfr_part_number: MCS04020Z0000ZE000; Mistral Part No: 110018030052-R; Package: 0402; Part_type: RESISTORS\FIXED; Project: DRDL_ITS2-SC; RoHS: RoHS; SIGNAL_MODEL: INS23888567; Temperature: -55°C+155°C; Tolerance: NA; Voltage: NA; Wattage: 1/10W; Weight: 0.65mg; Datasheet: Y:\MIS_DATABASE\DATASHEETS\RESISTORS\MCTXXXXC-SER.PDF
R386-R391 = RESISTOR: RES 100K 1/16W 5% 0402; Chkd/date: VASANTHA/130516; Crtd /date: VASANTHA/130516; Custom_Duty: 15%; Customs_HS_Code: 85332119; Distributor_name: DIGIKEY; Distributor_part_number: A121521CT-ND; Footprint Path: Y:\MIS_DATABASE\Library\ALTIUM_TOOL\PCB_FOOTPRINTS\Altium_Footprint_Lib.PcbLib; Height: 0.40MM; Library Path: Y:\MIS_DATABASE\Library\ALTIUM_TOOL\SCHEMATICS_PARTS\MS_DISCRETE_Library.schlib; Mfr_name: TE CONNECTIVITY; Mfr_part_number: CRG0402J100K/10; Mistral Part No: 110019040062-R; Package: 0402; Part_type: RESISTORS\FIXED; Project: TMDXCSK368; RoHS: RoHS; Temperature: -55°C+125°C; Tolerance: 5%; Voltage: NA; Wattage: 1/16W; Weight: 0.65mg; Datasheet: Y:\MIS_DATABASE\DATASHEETS\RESISTORS\CRG-SERIES.PDF
SW2-SW4 = SW4_GDH02S04: SWITCH DIP SPST HALF PITCH 2POS SMD; Chkd/date: VASANTHA/080715; Crtd /date: VASANTHA/241221; Custom_Duty: 24%; Customs_HS_Code: 85369090; Distributor_name: DIGIKEY; Distributor_part_number: CT2182LPST-ND; Height: 2.65MM; Mfr_name: CTS; Mistral Part No: 130014120040-R; Package: SMD; Part_type: ELECTRO-MECHANICAL\SWITCH; Project: FREE SCALE POM; RoHS: RoHS; Temperature: -55°C+85°C; Tolerance: NA; Voltage: NA; Wattage: NA; Weight: NA; Datasheet: Y:\MIS_DATABASE\DATASHEETS\MISC\SWITCHES\128-12LPST.PDF
U45-U47 = TLIN1022DMTTQ1_VSON14: IC DUAL LOCAL INTERCONNECT NETWORK TRANSCEIVER WITH DOMINANT STATE TIMEOUT VSON14; Chkd/date: MANIRAJA/230819; Crtd /date: MANIRAJA/230819; Custom_Duty: 15%; Customs_HS_Code: 85423100; Distributor_name: DIGIKEY; Distributor_part_number: 296-51677-1-ND; Footprint Path: Y:\MIS_DATABASE\Library\ALTIUM_TOOL\PCB_FOOTPRINTS\Altium_Footprint_Lib.PcbLib; Height: 0.90MM; Library Path: Y:\MIS_DATABASE\Library\ALTIUM_TOOL\SCHEMATICS_PARTS\MS_LINEDRIVERRECEIVER_Library.schlib; Mfr_name: TEXAS INSTRUMENTS; Mistral Part No: 141019080012-R; Package: VSON14; Part_type: ICS\DIGITAL\BUSTRANSCEIVER; Project: TI_J7ES_GESI_EXP_BOARD; RoHS: RoHS; Temperature: -40°C+125°C; Tolerance: NA; Voltage: NA; Wattage: NA; Weight: 37.3mg; Datasheet: Y:\MIS_DATABASE\DATASHEETS\ICS\DIGITAL\BUSTRANSCEIVER\TLIN1022-Q1.PDF
FID1-FID6 = Fiducial
LBL1 LBL2 = ACCESSORY_THT-3-423-10: ACCESSORIE 1 WORKHORSE POLYSTER LABLE 0.25" X 1"; Chkd/date: MANIRAJA/270218; Crtd /date: ALVY/260218; Footprint Path: Y:\MIS_DATABASE\Library\ALTIUM_TOOL\PCB_FOOTPRINTS\Altium_Footprint_Lib.PcbLib; Library Path: Y:\MIS_DATABASE\Library\ALTIUM_TOOL\SCHEMATICS_PARTS\MS_MECHANICAL_Library.schlib; Mfr_name: BRADY; Mistral Part No: 160018020185; Part_type: ACCESSORIES; Project: TI_MAXIE_CPB
LOGO1 LOGO3 LOGO4 = TI_Logo
LOGO2 = FCC_disclaimer
MH1-MH4 = WASHER_FLAT: FLAT RETAINING WASHER FOR M3 NYLON; Chkd/date: MANIRAJA/160519; Crtd /date: ALVY/160519; Distributor_name: DIGIKEY; Distributor_part_number: RPC4978-ND; Mfr_name: ESSENTRA COMPONENTS; Mfr_part_number: RWM100A; Mistral Part No: 160019050020-R; Part_type: MECHANICAL\WASHERS; Project: J7ES_SOM_DUAL-LEO_PMIC; RoHS: RoHS; Datasheet: Y:\MIS_DATABASE\DATASHEETS\MISC\MECHANICAL\RWMXXXXA.PDF
PCB1 = ACCESSORY_PROC078: PROC084 BARE PCB REV E3; Mfr_name: ANY

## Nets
DGND: C193.2 C194.2 C195.2 C196.2 C197.2 C198.2 C199.2 C200.2 C201.2 C202.2 C203.2 C204.2 C205.2 C206.2 C207.2 J25.4 J26.4 J27.4 R150.1 R386.1 R387.1 R388.1 R389.1 R390.1 R391.1 U45.8(GND) U45.15(EP) U46.8(GND) U46.15(EP) U47.8(GND) U47.15(EP) ; also on sheet 8 9 10 11 12 13 14 15 16 17 18 19 20 21 22 23 24
V12V0_VSUP1: C193.1 C194.1 C195.1 D7.2(A) D8.1(K) D9.2(A) D10.1(K) U45.10(VSUP)
V12V0_VSUP2: C198.1 C199.1 C200.1 D11.2(A) D12.1(K) D13.2(A) D14.1(K) U46.10(VSUP)
V12V0_VSUP3: C203.1 C204.1 C205.1 D15.2(A) D16.1(K) D17.2(A) D18.1(K) U47.10(VSUP)
VBAT_LIN1: D10.2(A) J25.1
VBAT_LIN2: D14.2(A) J26.1
VBAT_LIN3: D18.2(A) J27.1
VCC_3V3: R144.2 R364.2 R365.2 R372.2 R373.2 R380.2 R381.2 ; also on sheet 8 9 10 11 12 13 14 15 16 17 18 19 20 22 23 24
VCC_12V0: D8.2(A) D12.2(A) D16.2(A) ; also on sheet 8 23
GPIO_LIN_EN: R144.1 R150.2 U45.2(EN1) U45.5(EN2) U46.2(EN1) U46.5(EN2) U47.2(EN1) U47.5(EN2) ; also on sheet 8
LIN1_DATA: C196.1 J25.2 SW2.3 U45.13(LIN1)
LIN1_RXD: R364.1 R367.2 U45.1(RXD1)
LIN1_TXD: R366.2 R387.2 U45.3(TXD1)
LIN1_UART_RXD: R367.1 ; also on sheet 8
LIN1_UART_TXD: R366.1 ; also on sheet 8
LIN2_DATA: C197.1 J25.3 SW2.4 U45.9(LIN2)
LIN2_RXD: R365.1 R369.2 U45.4(RXD2)
LIN2_TXD: R368.2 R386.2 U45.7(TXD2)
LIN2_UART_RXD: R369.1 ; also on sheet 8
LIN2_UART_TXD: R368.1 ; also on sheet 8
LIN3_DATA: C201.1 J26.2 SW3.3 U46.13(LIN1)
LIN3_RXD: R372.1 R375.2 U46.1(RXD1)
LIN3_TXD: R374.2 R389.2 U46.3(TXD1)
LIN3_UART_RXD: R375.1 ; also on sheet 8
LIN3_UART_TXD: R374.1 ; also on sheet 8
LIN4_DATA: C202.1 J26.3 SW3.4 U46.9(LIN2)
LIN4_RXD: R373.1 R377.2 U46.4(RXD2)
LIN4_TXD: R376.2 R388.2 U46.7(TXD2)
LIN4_UART_RXD: R377.1 ; also on sheet 8
LIN4_UART_TXD: R376.1 ; also on sheet 8
LIN5_DATA: C206.1 J27.2 SW4.3 U47.13(LIN1)
LIN5_RXD: R380.1 R383.2 U47.1(RXD1)
LIN5_TXD: R382.2 R390.2 U47.3(TXD1)
LIN5_UART_RXD: R383.1 ; also on sheet 8
LIN5_UART_TXD: R382.1 ; also on sheet 8
LIN6_DATA: C207.1 J27.3 SW4.4 U47.9(LIN2)
LIN6_RXD: R381.1 R385.2 U47.4(RXD2)
LIN6_TXD: R384.2 R391.2 U47.7(TXD2)
LIN6_UART_RXD: R385.1 ; also on sheet 8
LIN6_UART_TXD: R384.1 ; also on sheet 8
N24160349: D7.1(K) R362.1
N24160363: R362.2 SW2.2
N24208258: R363.2 SW2.1
N24208263: D9.1(K) R363.1
N24217026: R371.2 SW3.1
N24217030: D13.1(K) R371.1
N24217148: D11.1(K) R370.1
N24217172: R370.2 SW3.2
N24217959: R379.2 SW4.1
N24217963: D17.1(K) R379.1
N24218081: D15.1(K) R378.1
N24218105: R378.2 SW4.2

Not connected (* = marked no-connect by the designer): U45 6(NC1) 11(NC2) 12(NC3) 14(NC4); U46 6(NC1) 11(NC2) 12(NC3) 14(NC4); U47 6(NC1) 11(NC2) 12(NC3) 14(NC4)

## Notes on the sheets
sheet 1
- LIN INTERFACE - 03
- (VBAT_LIN: 4V to 45V)
- Silkscreen: "LIN5 & 6"
- LIN MASTER MODE
- SW4 - CLOSE
- LIN SLAVE MODE
- SW4 - OPEN
sheet 2
- LIN INTERFACE - 02
- (VBAT_LIN: 4V to 45V)
- Silkscreen: "LIN3 & 4"
- LIN MASTER MODE
- SW3 - CLOSE
- LIN SLAVE MODE
- SW3 - OPEN
sheet 3
- LIN INTERFACE - 01
- (VBAT_LIN: 4V to 45V)
- Silkscreen: "LIN1 & 2"
- LIN MASTER MODE
- Switch - CLOSE
- LIN SLAVE MODE
- Switch - OPEN
sheet 4
- HARDWARE SCHEMATICS
- ASSEMBLY NOTES
- FIDUCIALS
- 1. All MSL components should be baked as per JEDEC
  standard.
  2. PCB should be baked at 120 degree for 8 hours.
  3. Board assembly must comply with workmanship standards.
  IPC-A-610 Class 2, unless otherwise specified.
  4. These assemblies are ESD sensitive, ESD precautions
  shall be observed.
  5. These assemblies must be clean and free from flux and
  all contaminants. Use of no clean flux is not acceptable.
  6. Provide serial numbers to the assembled boards for
  identification.
  7. The assembled board are wrapped in ESD Covers(individual)
  and packed securely before shipment.
- WASHERS
- BARE PCB
- LABELS
- Board Serial No.
- LOGOs
- Texas Intruments
- For Evaluation only; not FCC approved for resale
- WEEE Mark
- CE Mark
- Assembly Revision.
sheet 5
- GESI EXPANSION BOARD
- TABLE OF CONTENTS
- REV
- E3A
- PAGE
- CONTENTS
- VER
- 0.2
- 01
- TABLE OF CONTENTS
- 02
- REVISION HISTORY
- 03
- BLOCK DIAGRAM
- 04
- EXPANSION CONNECTOR
- 05
- PRG1 MUX - 01
- 06
- PRG1 MUX - 02
- 07
- TEST CONNECTOR & EEPROM
- 08
- MDIO MDC - MUX
- 09
- PRG0 GB_ETHERNET RGMII 1
- 10
- PRG0 GB_ETHERNET RGMII 2
- 11
- PRG1 GB_ETHERNET RGMII 1
- 12
- PRG1 GB_ETHERNET RGMII 2
- 13
- CAN TRANSCEIVERS - 01
- 14
- CAN TRANSCEIVERS - 02
- 15
- LIN INTERFACE -01
- 16
- LIN INTERFACE -02
- 17
- LIN INTERFACE -03
- 18
- RS485 INTERFACE
- 19
- USS/IMU & MOTOR CONTROL
- 20
- BOOSTERPACK HEADER
- 21
- ADC IN
- 22
- RMII PHY INTERFACE
- 23
- POWER SUPPLY
- 24
- HARDWARE SCHEMATICS
sheet 6
- REVISION HISTORY
- VER #
- DATE
- DESCRIPTION OF CHANGES
- AUTHOR
- REVIEWED  BY
- APPROVED  BY
- Drafted from "PROC084E3_SCH, VER: 1.3".
- 0.1
- 21-NOV-2019
- Mistral Design Team
- TP62 & TP63 moved to DNI and Hardware Schematic page Updated
- 0.2
- 26-NOV-2019
- Updated the RGMII REF CLOCK Buffer U31 Part# to 651SDCGI
- Mistral Design Team
sheet 7
- BLOCK DIAGRAM
